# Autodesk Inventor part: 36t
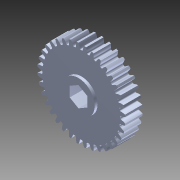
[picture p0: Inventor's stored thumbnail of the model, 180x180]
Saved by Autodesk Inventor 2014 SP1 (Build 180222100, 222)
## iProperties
Created: 2014-11
Part Number: 36t
Material: Aluminum 6061
Document SubType Name: Modeling
Designer: Michael
Density: 2.71 g/cm^3
Appearance: Aluminum - Flat
Title: 217-3213-STEP.STEP
Description: STEP AP214
Creation Date: 2013-12-09
Sending System: SolidWorks 2013
Preprocessor: SwSTEP 2.0
Author: Michael
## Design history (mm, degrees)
node "36t1"
node "Cut-Extrude2"
node "Base1"
